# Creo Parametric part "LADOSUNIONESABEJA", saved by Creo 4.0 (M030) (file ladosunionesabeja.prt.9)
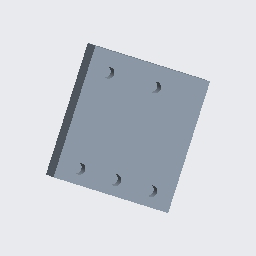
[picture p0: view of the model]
Units: millimeter Newton Second (mmNs); MM, TONNE, SECS

Created from: MMNS_PART_SOLID.PRT

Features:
  1. datum plane "RIGHT"
  2. datum plane "TOP"
  3. datum plane "FRONT"
  4. coordinate system
  5. sketch "Sketch 1"
  6. extrusion "Extrude 1"
  7. pattern "Pattern 1"
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
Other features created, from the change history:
  hole "Hole 1"
  hole "Hole 1 [2]"
  hole "Hole 1 [3]"
  hole "Hole 2"
  pattern "Patrón 2"
  hole "Taladro 2 [2]"
  hole "Hole 3"
  pattern "Pattern 3"
  hole "Hole 3 [2]"

Surfaces: 13 plane, 7 cylinder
